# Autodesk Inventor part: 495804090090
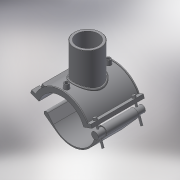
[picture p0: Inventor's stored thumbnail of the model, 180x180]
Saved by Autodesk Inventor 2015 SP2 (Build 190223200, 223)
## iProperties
Created: 2017-07
Part Number: 495804090090
Material: Generic
Description: PLASSON BRANCH SADDLE 90-90
Document SubType Name: Modeling
Designer: KIM
Density: 1 g/cm^3
Appearance: Default
Author: KIM
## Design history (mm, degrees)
derived "495804.ipt"
feature "Solid1::495804.ipt"
feature "Solid2::495804.ipt"
tag "TaggingFeature1"
body "Solid1"
body "Solid2"
other parameters: "d2" = 139, "d3" = 22.5, "d4" = 176, "d5" = 0, "d6" = 0.1, "d8" = 0, "d19" = 6, "d20" = 6, "d21" = 105.6, "d23" = 0, "d24" = 52.8, "d26" = 0, "d27" = 3, "d28" = 3, "d29" = 3, "d31" = 6, "d32" = 0, "d33" = 0, "d34" = 0.6, "d40" = 62.4, "d41" = 99, "d43" = 0, "d45" = 0, "d47" = 165, "d50" = 0, "d70" = 15, "d72" = 0, "d73" = 6, "d75" = 5, "d76" = 0, "d77" = 4.5, "d78" = 75, "d79" = 15, "d80" = 70.4, "d82" = 5 deg, "d84" = 4, "d85" = 14, "d86" = 0, "d87" = 3, "d88" = 0, "d89" = 1, "d90" = 1, "d91" = 140.8, "d92" = 0, "d93" = 0.5, "d94" = 47.36842, "d96" = 122.4, "d97" = 3.52, "d98" = 0, "d102" = 2.7, "d103" = 72, "d105" = 0, "d109" = -35, "d117" = 0.9, "d120" = 140 deg, "d121" = 24.228, "d122" = 20 deg, "d124" = 72, "d126" = 0, "d143" = 94.5, "d150" = 16.2, "d159" = 6, "d161" = 2.25, "d162" = 105.6, "d163" = 0, "d167" = 18, "d168" = 54.54545, "d173" = 1, "d175" = 45, "d176" = 20 deg, "d177" = 6.3, "d178" = 24, "d180" = 0, "d185" = 57.2, "d186" = 57.2, "d188" = 9, "d189" = 6.3, "d190" = 0, "d200" = 15, "d202" = 0, "d216" = 158.4, "d217" = 0, "d221" = 65.12, "d222" = 6.3, "d223" = 3.78, "d224" = 45, "d225" = 3.78, "d227" = 12.96, "d230" = 65.7, "d236" = 20 deg, "d237" = 65, "d238" = 20 deg, "d239" = 6.3, "B_" = 139, "H_" = 105, "L_" = 176, "d_t" = 6, "d148" = 2.25, "d160" = 2.25
